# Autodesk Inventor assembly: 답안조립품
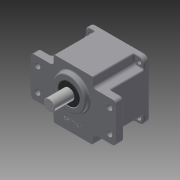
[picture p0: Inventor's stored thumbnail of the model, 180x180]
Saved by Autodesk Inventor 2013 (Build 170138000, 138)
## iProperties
Created: 2015-07
Part Number: 답안조립품
Document SubType Name: Assembly
Designer: user
Author: user
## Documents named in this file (12)
- C:\Users\user\Desktop\450734V1004\답안조립품.iam
- C:\Users\user\Desktop\450734V1004\본체.ipt
- C:\Users\user\Desktop\450734V1004\베어링 6003.ipt
- 베어링 6003.ipt
- C:\Users\user\Desktop\450734V1004\메인축.ipt
- C:\Users\user\Desktop\450734V1004\베어링 608.ipt
- 베어링 608.ipt
- C:\Users\user\Desktop\450734V1004\커버.ipt
- C:\Users\user\Desktop\450734V1004\서브축.ipt
- C:\Users\user\Desktop\450734V1004\오일실 17x32x8.ipt
- C:\Users\user\Desktop\450734V1004\오일실 8x22x7.ipt
- C:\Users\user\Desktop\450734V1004\M4x0.5x16.ipt
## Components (4 placed, 1 different names)
1. M4x0.5x12:1
2. M4x0.5x12:2
3. M4x0.5x12:3
4. M4x0.5x12:4
